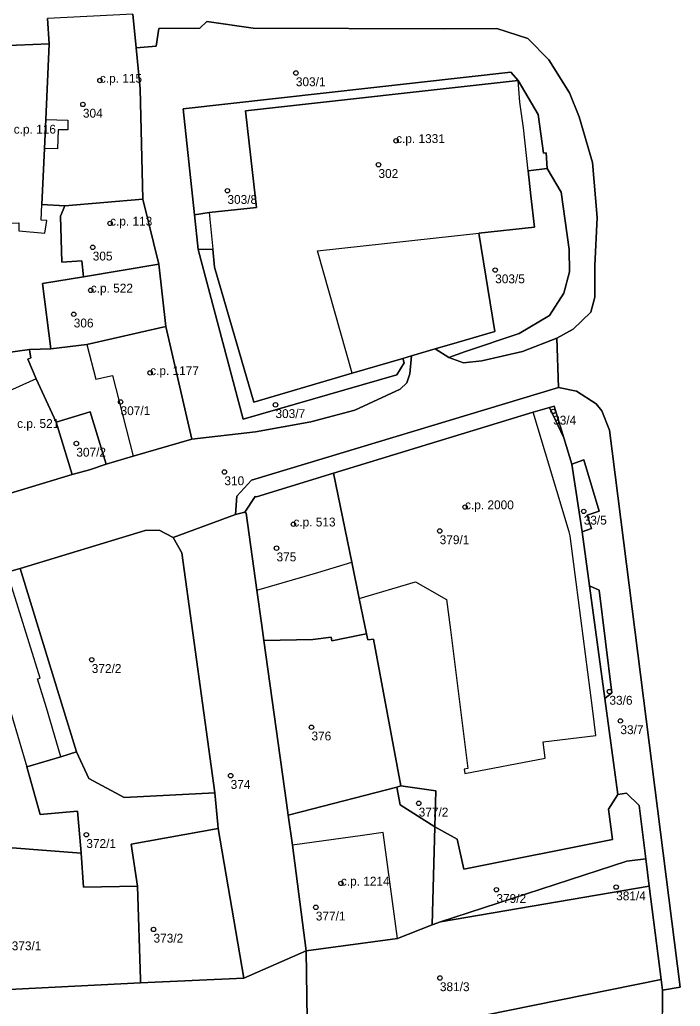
# Model space of a CAD drawing. Extents: x -878211 to -870363, y -1058464 to -1052522.
# Drawn here: x -874543.8 to -874469.2, y -1056260.7 to -1056149.3 of the extents above; entities that cross this region are included whole.
import ezdxf

# ---------------------------------------------------------------- set-up
doc = ezdxf.new("R2010")
doc.units = 0
for name, color, linetype in [('Definiční body', 7, 'Continuous'), ('Hranice parcel', 7, 'Continuous'), ('Polygon budovy', 7, 'Continuous'), ('Polygon parcely', 7, 'Continuous')]:
    doc.layers.add(name, color=color, linetype=linetype)

msp = doc.modelspace()

# ---------------------------------------------------------------- linework, layer by layer
at = {"layer": 'Definiční body'}
for centre in [(-874534.73, -1056156.19994), (-874512.62, -1056155.34994), (-874536.65, -1056158.89994), (-874501.31, -1056163.00994), (-874503.3, -1056165.70994), (-874520.34, -1056168.63994), (-874533.58, -1056172.32994), (-874535.54, -1056175.02994), (-874490.13, -1056177.59994), (-874535.76, -1056179.88994), (-874537.68, -1056182.58994), (-874529.06, -1056189.20994), (-874532.4, -1056192.48994), (-874514.92, -1056192.81994), (-874483.59, -1056193.55994), (-874537.39, -1056197.17994), (-874520.68, -1056200.39994), (-874493.53, -1056204.35994), (-874480.14, -1056204.84994), (-874512.9, -1056206.29994), (-874496.39, -1056207.05994), (-874514.8, -1056208.99994), (-874535.65, -1056221.59994), (-874477.24, -1056225.18994), (-874476, -1056228.50994), (-874510.86, -1056229.21994), (-874519.98, -1056234.68994), (-874498.76, -1056237.80994), (-874536.26, -1056241.35994), (-874507.54, -1056246.84994), (-874489.99, -1056247.56994), (-874476.48, -1056247.26994), (-874510.37, -1056249.54994), (-874528.68, -1056252.04994), (-874496.37, -1056257.52994)]:
    msp.add_circle(centre, 0.25, dxfattribs=at)
at = {"layer": 'Hranice parcel'}
msp.add_line((-874471.42, -1056257.72), (-874471.27, -1056258.91), dxfattribs=at)
for points in [[(-874471.27, -1056258.91), (-874469.25, -1056258.58), (-874477.25, -1056195.68), (-874478.09, -1056193.48), (-874478.75, -1056192.69), (-874480.94, -1056191.28), (-874483, -1056190.87)], [(-874471.6, -1056263.9), (-874471.26, -1056261.41), (-874471.27, -1056258.91)]]:
    msp.add_lwpolyline(points, dxfattribs=at)
at = {"layer": 'Polygon budovy'}
for points in [[(-874541.27, -1056170.21), (-874538.67, -1056170.35), (-874529.9, -1056169.59), (-874530.2, -1056157.14), (-874530.65, -1056152.49), (-874531.02, -1056148.7), (-874540.65, -1056149.18), (-874540.45, -1056152.04), (-874540.84, -1056160.61), (-874538.36, -1056160.66), (-874538.35, -1056161.75), (-874539.43, -1056161.76), (-874539.53, -1056163.9), (-874540.98, -1056163.86)], [(-874547.86, -1056152.35), (-874548.58, -1056172.56), (-874547.76, -1056172.55), (-874547.75, -1056172.39), (-874543.88, -1056172.28), (-874543.87, -1056173.16), (-874540.96, -1056173.44), (-874540.72, -1056172.01), (-874541.36, -1056171.98), (-874541.27, -1056170.21), (-874540.98, -1056163.86), (-874540.84, -1056160.61), (-874540.45, -1056152.04)], [(-874491.97, -1056173.43), (-874485.71, -1056172.74), (-874486.11, -1056169.2), (-874486.42, -1056166.41), (-874486.95, -1056161.54), (-874487.35, -1056158.66), (-874487.53, -1056156.2), (-874518.31, -1056159.63), (-874517.7, -1056164.93), (-874517.08, -1056170.52), (-874522.4, -1056171.1), (-874522, -1056175.25), (-874521.81, -1056177.26), (-874517.38, -1056192.51), (-874506.27, -1056189.25), (-874510.17, -1056175.44)], [(-874538.67, -1056170.35), (-874539.19, -1056171.5), (-874539.02, -1056176.7), (-874536.78, -1056176.56), (-874536.58, -1056178.38), (-874528.1, -1056176.95), (-874529.9, -1056169.59)], [(-874536.58, -1056178.38), (-874541.2, -1056179.12), (-874540.27, -1056186.5), (-874536.21, -1056186), (-874527.31, -1056183.96), (-874528.1, -1056176.95)], [(-874536.21, -1056186), (-874535.19, -1056189.91), (-874533.31, -1056189.51), (-874530.98, -1056198.61), (-874524.36, -1056196.68), (-874527.31, -1056183.96)], [(-874550.54, -1056197.58), (-874548.69, -1056203.94), (-874537.85, -1056200.68), (-874539.65, -1056194.78), (-874541.93, -1056189.88), (-874545.36, -1056191.41), (-874549.27, -1056192.71), (-874548.7, -1056196.38), (-874548.56, -1056196.87)], [(-874506.29, -1056210.58), (-874505.47, -1056214.67), (-874499.11, -1056212.82), (-874495.64, -1056214.8), (-874495.19, -1056218.22), (-874493.22, -1056233.88), (-874493.64, -1056233.95), (-874493.55, -1056234.46), (-874484.48, -1056232.73), (-874484.7, -1056230.87), (-874478.76, -1056230.17), (-874479.17, -1056227.06), (-874480.99, -1056212.85), (-874481.62, -1056207.9), (-874481.69, -1056207.61), (-874481.78, -1056207.15), (-874485.86, -1056193.66), (-874508.37, -1056200.53)], [(-874517.23, -1056203.16), (-874518.36, -1056204.95), (-874518.23, -1056205.05), (-874517.03, -1056213.73), (-874510.15, -1056211.74), (-874506.29, -1056210.58), (-874508.37, -1056200.53), (-874517.08, -1056203.21)], [(-874558.48, -1056215.79), (-874557.61, -1056222.58), (-874556.71, -1056222.3), (-874554.77, -1056228.61), (-874548.45, -1056226.67), (-874547.49, -1056225.47), (-874545.58, -1056224.9), (-874542.96, -1056233.7), (-874539.15, -1056232.56), (-874540.77, -1056227.04), (-874541.77, -1056223.76), (-874541.48, -1056223.67), (-874545.18, -1056211.72)], [(-874513.01, -1056242.52), (-874511.47, -1056254.46), (-874501.14, -1056253.07), (-874502.77, -1056241.1), (-874505.12, -1056241.45)]]:
    msp.add_lwpolyline(points, close=True, dxfattribs=at)
at = {"layer": 'Polygon parcely'}
for points in [[(-874560.17, -1056153.55), (-874553.38, -1056152.63), (-874547.86, -1056152.35), (-874540.45, -1056152.04), (-874540.65, -1056149.18)], [(-874531.02, -1056148.7), (-874530.65, -1056152.49), (-874528.4, -1056152.31), (-874528.08, -1056150.34), (-874523.45, -1056150.3), (-874522.65, -1056149.54), (-874517.45, -1056150.29), (-874495.87, -1056150.38), (-874489.96, -1056150.32), (-874486.45, -1056151.47), (-874484.09, -1056153.86), (-874481.73, -1056157.59), (-874480.67, -1056160.29), (-874479.15, -1056165.45), (-874478.62, -1056171.66), (-874478.87, -1056177.09), (-874478.9, -1056180.66), (-874479.34, -1056182.37), (-874481.33, -1056184.27), (-874483.16, -1056185.29), (-874483, -1056190.87), (-874480.94, -1056191.28), (-874478.75, -1056192.69), (-874478.09, -1056193.48), (-874477.25, -1056195.68), (-874469.25, -1056258.58), (-874471.27, -1056258.91), (-874471.26, -1056261.41)], [(-874545.18, -1056211.72), (-874543.73, -1056211.28), (-874529.61, -1056206.99), (-874528.06, -1056206.96), (-874526.45, -1056207.79), (-874519.42, -1056205.21), (-874519.27, -1056203.12), (-874517.61, -1056201.33), (-874483, -1056190.87), (-874483.16, -1056185.29), (-874487.04, -1056186.81), (-874491.64, -1056187.85), (-874493.72, -1056188.06), (-874495.36, -1056187.47), (-874496.9, -1056186.49), (-874499.56, -1056187.28), (-874499.77, -1056189.33), (-874500.11, -1056190.32), (-874500.86, -1056191.04), (-874505.95, -1056193.43), (-874510.92, -1056194.73), (-874517.19, -1056195.88), (-874524.36, -1056196.68), (-874530.98, -1056198.61), (-874534.02, -1056199.53), (-874535.92, -1056200.14), (-874537.85, -1056200.68), (-874548.69, -1056203.94)], [(-874545.12, -1056280.87), (-874543.06, -1056286.68), (-874540.32, -1056286.53), (-874541.62, -1056279.97), (-874541.47, -1056279.94), (-874542.73, -1056273.6), (-874543.63, -1056268.66), (-874530.34, -1056266.81), (-874528.28, -1056266.57), (-874526.87, -1056269.23), (-874523.39, -1056268.63), (-874519.92, -1056268.04), (-874516.96, -1056267.96), (-874511.26, -1056267.37), (-874511.47, -1056254.46), (-874518.51, -1056257.56), (-874530.14, -1056258.09), (-874549.43, -1056259.05)]]:
    msp.add_lwpolyline(points, dxfattribs=at)
for points in [[(-874529.9, -1056169.59), (-874530.2, -1056157.14), (-874530.65, -1056152.49), (-874531.02, -1056148.7), (-874540.65, -1056149.18), (-874540.45, -1056152.04), (-874540.84, -1056160.61), (-874540.98, -1056163.86), (-874541.27, -1056170.21), (-874538.67, -1056170.35)], [(-874487.41, -1056184.77), (-874493.49, -1056186.79), (-874495.36, -1056187.47), (-874493.72, -1056188.06), (-874491.64, -1056187.85), (-874487.04, -1056186.81), (-874483.16, -1056185.29), (-874481.33, -1056184.27), (-874479.34, -1056182.37), (-874478.9, -1056180.66), (-874478.87, -1056177.09), (-874478.62, -1056171.66), (-874479.15, -1056165.45), (-874480.67, -1056160.29), (-874481.73, -1056157.59), (-874484.09, -1056153.86), (-874486.45, -1056151.47), (-874489.96, -1056150.32), (-874495.87, -1056150.38), (-874517.45, -1056150.29), (-874522.65, -1056149.54), (-874523.45, -1056150.3), (-874528.08, -1056150.34), (-874528.4, -1056152.31), (-874530.65, -1056152.49), (-874530.2, -1056157.14), (-874529.9, -1056169.59), (-874528.1, -1056176.95), (-874527.31, -1056183.96), (-874524.36, -1056196.68), (-874517.19, -1056195.88), (-874510.92, -1056194.73), (-874505.95, -1056193.43), (-874500.86, -1056191.04), (-874500.11, -1056190.32), (-874499.77, -1056189.33), (-874499.56, -1056187.28), (-874500.56, -1056187.57), (-874500.4, -1056188.06), (-874501.22, -1056189.43), (-874518.55, -1056194.45), (-874523.66, -1056175.26), (-874524.04, -1056171.35), (-874525.34, -1056159.38), (-874488.37, -1056155.27), (-874487.53, -1056156.2), (-874485.27, -1056160.02), (-874484.69, -1056164.4), (-874484.37, -1056164.37), (-874484.25, -1056166.14), (-874482.7, -1056168.8), (-874481.79, -1056175.28), (-874481.73, -1056177.79), (-874482.37, -1056180.21), (-874483.99, -1056182.74)], [(-874542.66, -1056186.56), (-874540.27, -1056186.5), (-874541.2, -1056179.12), (-874536.58, -1056178.38), (-874536.78, -1056176.56), (-874539.02, -1056176.7), (-874539.19, -1056171.5), (-874538.67, -1056170.35), (-874541.27, -1056170.21), (-874540.98, -1056163.86), (-874540.84, -1056160.61), (-874540.45, -1056152.04), (-874547.86, -1056152.35), (-874548.58, -1056172.56), (-874548.69, -1056176.19), (-874548.85, -1056179.04), (-874548.19, -1056186.51), (-874548.12, -1056187.34)], [(-874524.04, -1056171.35), (-874522.4, -1056171.1), (-874517.08, -1056170.52), (-874517.7, -1056164.93), (-874518.31, -1056159.63), (-874487.53, -1056156.2), (-874488.37, -1056155.27), (-874525.34, -1056159.38)], [(-874485.71, -1056172.74), (-874486.11, -1056169.2), (-874486.42, -1056166.41), (-874484.25, -1056166.14), (-874484.37, -1056164.37), (-874484.69, -1056164.4), (-874485.27, -1056160.02), (-874487.53, -1056156.2), (-874518.31, -1056159.63), (-874517.7, -1056164.93), (-874517.08, -1056170.52), (-874522.4, -1056171.1), (-874524.04, -1056171.35), (-874523.66, -1056175.26), (-874522, -1056175.25), (-874521.81, -1056177.26), (-874517.38, -1056192.51), (-874506.27, -1056189.25), (-874500.56, -1056187.57), (-874499.56, -1056187.28), (-874496.9, -1056186.49), (-874494.43, -1056185.77), (-874490.16, -1056184.53), (-874491.97, -1056173.43)], [(-874495.36, -1056187.47), (-874493.49, -1056186.79), (-874487.41, -1056184.77), (-874483.99, -1056182.74), (-874482.37, -1056180.21), (-874481.73, -1056177.79), (-874481.79, -1056175.28), (-874482.7, -1056168.8), (-874484.25, -1056166.14), (-874486.42, -1056166.41), (-874486.11, -1056169.2), (-874485.71, -1056172.74), (-874491.97, -1056173.43), (-874490.16, -1056184.53), (-874494.43, -1056185.77), (-874496.9, -1056186.49)], [(-874528.1, -1056176.95), (-874529.9, -1056169.59), (-874538.67, -1056170.35), (-874539.19, -1056171.5), (-874539.02, -1056176.7), (-874536.78, -1056176.56), (-874536.58, -1056178.38)], [(-874500.56, -1056187.57), (-874506.27, -1056189.25), (-874517.38, -1056192.51), (-874521.81, -1056177.26), (-874522, -1056175.25), (-874523.66, -1056175.26), (-874518.55, -1056194.45), (-874501.22, -1056189.43), (-874500.4, -1056188.06)], [(-874540.27, -1056186.5), (-874536.21, -1056186), (-874527.31, -1056183.96), (-874528.1, -1056176.95), (-874536.58, -1056178.38), (-874541.2, -1056179.12)], [(-874530.98, -1056198.61), (-874524.36, -1056196.68), (-874527.31, -1056183.96), (-874536.21, -1056186), (-874540.27, -1056186.5), (-874542.66, -1056186.56), (-874542.6, -1056187.08), (-874542.52, -1056187.5), (-874542.86, -1056187.67), (-874541.93, -1056189.88), (-874539.65, -1056194.78), (-874535.83, -1056193.61), (-874534.02, -1056199.53)], [(-874539.65, -1056194.78), (-874541.93, -1056189.88), (-874542.86, -1056187.67), (-874542.52, -1056187.5), (-874542.6, -1056187.08), (-874542.66, -1056186.56), (-874548.12, -1056187.34), (-874550.17, -1056187.63), (-874549.27, -1056192.71), (-874548.7, -1056196.38), (-874550.7, -1056196.94), (-874550.54, -1056197.58), (-874548.69, -1056203.94), (-874537.85, -1056200.68)], [(-874473.14, -1056244.07), (-874472.75, -1056247.18), (-874471.42, -1056257.72), (-874471.27, -1056258.91), (-874469.25, -1056258.58), (-874477.25, -1056195.68), (-874478.09, -1056193.48), (-874478.75, -1056192.69), (-874480.94, -1056191.28), (-874483, -1056190.87), (-874517.61, -1056201.33), (-874519.27, -1056203.12), (-874519.42, -1056205.21), (-874518.36, -1056204.95), (-874517.23, -1056203.16), (-874517.08, -1056203.21), (-874508.37, -1056200.53), (-874485.86, -1056193.66), (-874484.02, -1056193.13), (-874483.49, -1056192.98), (-874482.4, -1056196.54), (-874481.49, -1056199.53), (-874480.12, -1056199.04), (-874478.39, -1056204.84), (-874479.75, -1056205.26), (-874479.28, -1056206.79), (-874480.32, -1056207.15), (-874479.49, -1056213.27), (-874478.41, -1056213.75), (-874476.97, -1056225.35), (-874477.76, -1056225.97), (-874476.29, -1056236.8), (-874475.31, -1056236.66), (-874473.9, -1056238.06)], [(-874539.65, -1056194.78), (-874537.85, -1056200.68), (-874535.92, -1056200.14), (-874534.02, -1056199.53), (-874535.83, -1056193.61)], [(-874496.93, -1056240.45), (-874494.41, -1056241.87), (-874493.67, -1056245.23), (-874476.91, -1056241.88), (-874477.34, -1056238.48), (-874476.29, -1056236.8), (-874477.76, -1056225.97), (-874479.49, -1056213.27), (-874480.32, -1056207.15), (-874481.49, -1056199.53), (-874482.4, -1056196.54), (-874484.02, -1056193.13), (-874485.86, -1056193.66), (-874508.37, -1056200.53), (-874506.29, -1056210.58), (-874505.47, -1056214.67), (-874504.65, -1056218.66), (-874504.51, -1056219.35), (-874503.85, -1056219.27), (-874500.77, -1056235.84), (-874496.81, -1056236.4)], [(-874482.4, -1056196.54), (-874483.49, -1056192.98), (-874484.02, -1056193.13)], [(-874479.75, -1056205.26), (-874478.39, -1056204.84), (-874480.12, -1056199.04), (-874481.49, -1056199.53), (-874480.32, -1056207.15), (-874479.28, -1056206.79)], [(-874516.47, -1056217.74), (-874516.23, -1056219.43), (-874510.69, -1056219.31), (-874508.65, -1056219.04), (-874508.57, -1056219.48), (-874505.26, -1056218.79), (-874504.65, -1056218.66), (-874505.47, -1056214.67), (-874506.29, -1056210.58), (-874508.37, -1056200.53), (-874517.08, -1056203.21), (-874517.23, -1056203.16), (-874518.36, -1056204.95), (-874518.23, -1056205.05), (-874517.03, -1056213.73)], [(-874525.48, -1056209.54), (-874521.75, -1056236.61), (-874521.41, -1056240.22), (-874521.37, -1056240.67), (-874518.51, -1056257.56), (-874511.47, -1056254.46), (-874513.01, -1056242.52), (-874513.49, -1056239.14), (-874513.68, -1056237.76), (-874516.23, -1056219.43), (-874516.47, -1056217.74), (-874517.03, -1056213.73), (-874518.23, -1056205.05), (-874518.36, -1056204.95), (-874519.42, -1056205.21), (-874526.45, -1056207.79)], [(-874526.45, -1056207.79), (-874528.06, -1056206.96), (-874529.61, -1056206.99), (-874543.73, -1056211.28), (-874539.06, -1056226.52), (-874537.39, -1056231.99), (-874535.99, -1056234.99), (-874531.99, -1056237.17), (-874521.75, -1056236.61), (-874525.48, -1056209.54)], [(-874536.86, -1056243.43), (-874536.89, -1056242.96), (-874537.24, -1056238.7), (-874541.46, -1056239.07), (-874542.96, -1056233.7), (-874539.15, -1056232.56), (-874537.39, -1056231.99), (-874539.06, -1056226.52), (-874543.73, -1056211.28), (-874545.18, -1056211.72), (-874558.48, -1056215.79), (-874557.61, -1056222.58), (-874555.43, -1056230.05), (-874553.35, -1056238.4), (-874553.13, -1056242.34), (-874551.63, -1056242.39), (-874549.05, -1056242.48)], [(-874479.49, -1056213.27), (-874477.76, -1056225.97), (-874476.97, -1056225.35), (-874478.41, -1056213.75)], [(-874500.77, -1056235.84), (-874503.85, -1056219.27), (-874504.51, -1056219.35), (-874504.65, -1056218.66), (-874505.26, -1056218.79), (-874508.57, -1056219.48), (-874508.65, -1056219.04), (-874510.69, -1056219.31), (-874516.23, -1056219.43), (-874513.68, -1056237.76), (-874513.49, -1056239.14), (-874512.03, -1056238.77), (-874501.21, -1056236)], [(-874535.99, -1056234.99), (-874537.39, -1056231.99), (-874539.15, -1056232.56), (-874542.96, -1056233.7), (-874541.46, -1056239.07), (-874537.24, -1056238.7), (-874536.89, -1056242.96), (-874536.86, -1056243.43), (-874536.59, -1056247.27), (-874530.47, -1056247.16), (-874531.22, -1056242.44), (-874521.37, -1056240.67), (-874521.41, -1056240.22), (-874521.75, -1056236.61), (-874531.99, -1056237.17)], [(-874501.21, -1056236), (-874512.03, -1056238.77), (-874513.49, -1056239.14), (-874513.01, -1056242.52), (-874511.47, -1056254.46), (-874501.14, -1056253.07), (-874497.25, -1056251.52), (-874496.93, -1056240.45), (-874500.85, -1056237.98)], [(-874500.85, -1056237.98), (-874496.93, -1056240.45), (-874496.81, -1056236.4), (-874500.77, -1056235.84), (-874501.21, -1056236)], [(-874475.29, -1056244.34), (-874473.14, -1056244.07), (-874473.9, -1056238.06), (-874475.31, -1056236.66), (-874476.29, -1056236.8), (-874477.34, -1056238.48), (-874476.91, -1056241.88), (-874493.67, -1056245.23), (-874494.41, -1056241.87), (-874496.93, -1056240.45), (-874497.25, -1056251.52), (-874496.29, -1056251.21)], [(-874518.51, -1056257.56), (-874521.37, -1056240.67), (-874531.22, -1056242.44), (-874530.47, -1056247.16), (-874530.14, -1056257.72), (-874530.14, -1056258.09)], [(-874536.59, -1056247.27), (-874536.86, -1056243.43), (-874549.05, -1056242.48), (-874551.63, -1056242.39), (-874549.43, -1056259.05), (-874530.14, -1056258.09), (-874530.14, -1056257.72), (-874530.47, -1056247.16)], [(-874472.75, -1056247.18), (-874473.14, -1056244.07), (-874475.29, -1056244.34), (-874496.29, -1056251.21)], [(-874472.75, -1056247.18), (-874496.29, -1056251.21), (-874497.25, -1056251.52), (-874501.14, -1056253.07), (-874511.47, -1056254.46), (-874511.26, -1056267.37), (-874502.78, -1056264.06), (-874471.42, -1056257.72)], [(-874507.34, -1056279.88), (-874484.69, -1056273.16), (-874474.92, -1056269.69), (-874472.35, -1056267.13), (-874471.6, -1056263.9), (-874471.26, -1056261.41), (-874471.27, -1056258.91), (-874471.42, -1056257.72), (-874502.78, -1056264.06), (-874511.26, -1056267.37)]]:
    msp.add_lwpolyline(points, close=True, dxfattribs=at)

# ---------------------------------------------------------------- texts
at = {"layer": 'Definiční body'}
for s, p in [('c.p. 115', (-874534.73, -1056156.45)), ('303/1', (-874512.62, -1056156.839)), ('304', (-874536.65, -1056160.389)), ('c.p. 116', (-874544.45, -1056162.2)), ('c.p. 1331', (-874501.31, -1056163.26)), ('302', (-874503.3, -1056167.199)), ('303/8', (-874520.34, -1056170.129)), ('c.p. 113', (-874533.58, -1056172.58)), ('305', (-874535.54, -1056176.519)), ('303/5', (-874490.13, -1056179.089)), ('c.p. 522', (-874535.76, -1056180.139)), ('306', (-874537.68, -1056184.079)), ('c.p. 1177', (-874529.06, -1056189.46)), ('307/1', (-874532.4, -1056193.979)), ('303/7', (-874514.92, -1056194.309)), ('c.p. 521', (-874544.07, -1056195.429)), ('33/4', (-874483.59, -1056195.049)), ('307/2', (-874537.39, -1056198.669)), ('310', (-874520.68, -1056201.889)), ('c.p. 2000', (-874493.53, -1056204.61)), ('c.p. 513', (-874512.9, -1056206.55)), ('33/5', (-874480.14, -1056206.339)), ('379/1', (-874496.39, -1056208.549)), ('375', (-874514.8, -1056210.489)), ('372/2', (-874535.65, -1056223.089)), ('33/6', (-874477.24, -1056226.679)), ('33/7', (-874476, -1056229.999)), ('376', (-874510.86, -1056230.709)), ('374', (-874519.98, -1056236.179)), ('377/2', (-874498.76, -1056239.299)), ('372/1', (-874536.26, -1056242.849)), ('c.p. 1214', (-874507.54, -1056247.1)), ('379/2', (-874489.99, -1056249.059)), ('381/4', (-874476.48, -1056248.759)), ('377/1', (-874510.37, -1056251.039)), ('373/2', (-874528.68, -1056253.539)), ('373/1', (-874544.68, -1056254.399)), ('381/3', (-874496.37, -1056259.019))]:
    msp.add_text(s, height=0.999996, dxfattribs=at).set_placement(p)

doc.saveas('drawing.dxf')
